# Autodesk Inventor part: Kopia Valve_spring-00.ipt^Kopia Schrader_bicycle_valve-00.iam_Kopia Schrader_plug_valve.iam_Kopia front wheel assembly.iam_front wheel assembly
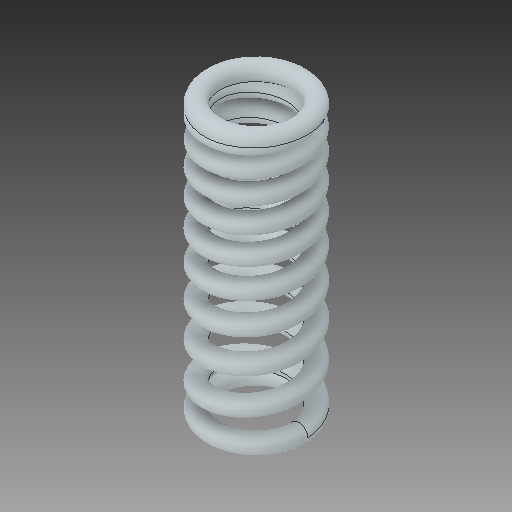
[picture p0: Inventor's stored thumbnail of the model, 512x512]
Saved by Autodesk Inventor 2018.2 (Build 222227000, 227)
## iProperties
Created: 2017-09
Part Number: Kopia Valve_spring-00.ipt^Kopia Schrader_bicycle_valve-00.iam_Kopia Schrader_plug_valve.iam_Kopia front wheel assembly.iam_front wheel assembly
Material: Ogólny
Document SubType Name: Modeling
Designer: Tomasz
Density: 1 g/cm^3
Appearance: Domyślna
Author: Tomasz
Sending System: SolidWorks 2017
Last Author: Tomasz
Last Saved: 2017-09-11
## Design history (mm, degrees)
feature "Valve_spring-00.ipt"
node "Bryła1"
